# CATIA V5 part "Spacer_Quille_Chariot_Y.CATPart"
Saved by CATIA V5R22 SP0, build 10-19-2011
Part number: Spacer_Quille_Chariot_Y
Bounding box of the stored display mesh (mm): x 0 to 28, y -5 to 5, z -5 to 5
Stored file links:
  U:\S9A\PER\CAO\Assemblage\Cadre\Chariot_Y\Spacer_Quille_Chariot_Y.CATPart
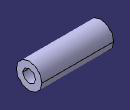
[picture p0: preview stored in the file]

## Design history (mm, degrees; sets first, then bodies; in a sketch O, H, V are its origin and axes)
Body1 (main body)
  Sketch1 on yz-plane, origin (0, 0, 0), H (0, 1, 0), V (0, 0, 1)
    circle A1 centre (0, 0) radius 2.5
    circle A2 centre (0, 0) radius 5
    radius A1 = 2.5
    radius A2 = 5
  Pad1: profile Sketch1, direction (1, 0, 0), length 28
